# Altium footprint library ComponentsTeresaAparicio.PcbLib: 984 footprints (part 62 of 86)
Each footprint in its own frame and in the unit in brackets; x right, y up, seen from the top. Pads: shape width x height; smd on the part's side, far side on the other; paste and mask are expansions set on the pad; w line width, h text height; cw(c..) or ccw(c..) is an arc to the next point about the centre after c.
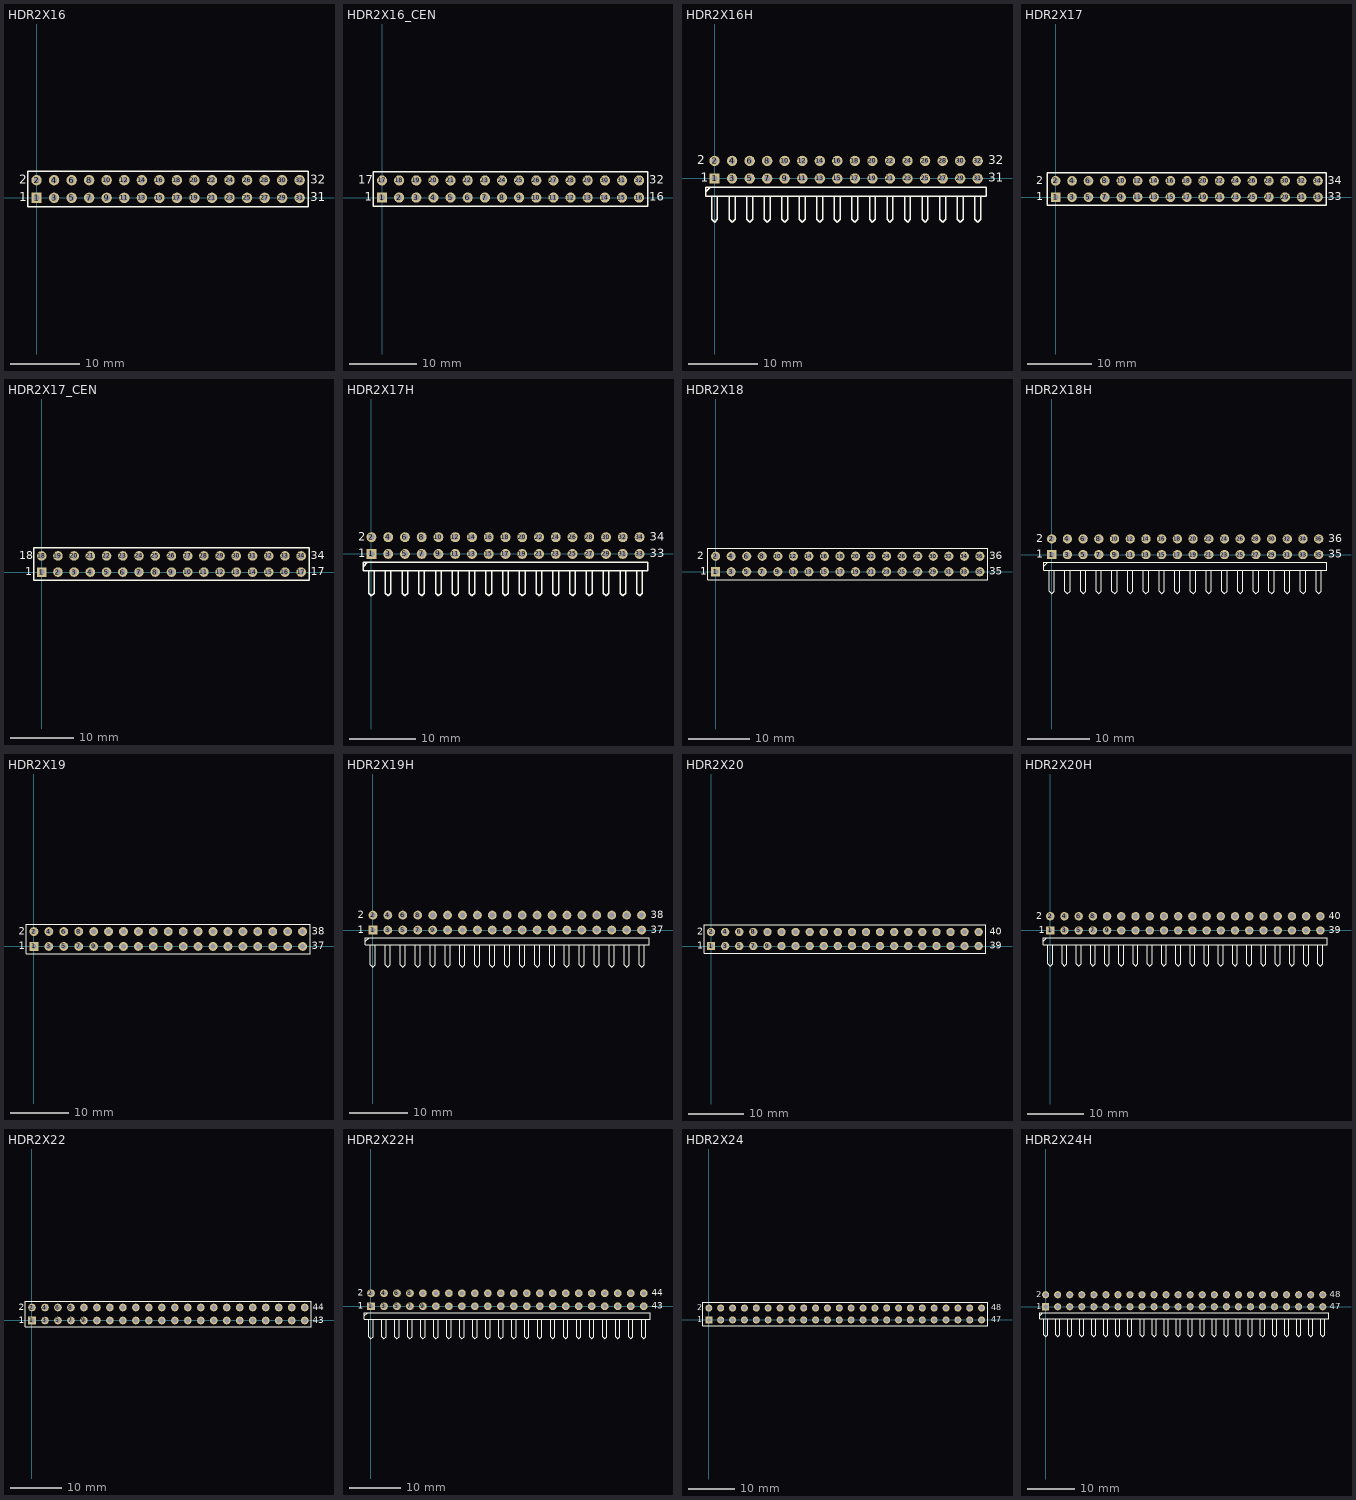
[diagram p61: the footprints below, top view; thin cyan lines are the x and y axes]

## HDR2X16 [mm] "Connector; Header; 16x2 Position"
pads (32):
  rect 1.5x1.5 hole 0.9: 1(0,0)
  round 1.5 hole 0.9: 2(0,2.54) 3(2.54,0) 4(2.54,2.54) 5(5.08,0) 6(5.08,2.54) 7(7.62,0) 8(7.62,2.54) 9(10.16,0) 10(10.16,2.54) 11(12.7,0) 12(12.7,2.54) 13(15.24,0) 14(15.24,2.54) 15(17.78,0) 16(17.78,2.54) 17(20.32,0) 18(20.32,2.54) 19(22.86,0) 20(22.86,2.54) 21(25.4,0) 22(25.4,2.54) 23(27.94,0) 24(27.94,2.54) 25(30.48,0) 26(30.48,2.54) 27(33.02,0) 28(33.02,2.54) 29(35.56,0) 30(35.56,2.54) 31(38.1,0) 32(38.1,2.54)
Top Overlay:
  lines w0.2: -1.27,-1.27 -1.27,3.81 39.37,3.81 39.37,-1.27 -1.27,-1.27
  text "32" at 39.624,2.032 h1.27
  text "31" at 39.624,-0.508 h1.27
  text "1" at -2.54,-0.508 h1.27
  text "2" at -2.54,2.032 h1.27

## HDR2X16_CEN [mm] "Connector; Header; 16x2 Position"
pads (32):
  rect 1.5x1.5 hole 0.9: 1(0,0)
  round 1.5 hole 0.9: 2(2.54,0) 3(5.08,0) 4(7.62,0) 5(10.16,0) 6(12.7,0) 7(15.24,0) 8(17.78,0) 9(20.32,0) 10(22.86,0) 11(25.4,0) 12(27.94,0) 13(30.48,0) 14(33.02,0) 15(35.56,0) 16(38.1,0) 17(0,2.54) 18(2.54,2.54) 19(5.08,2.54) 20(7.62,2.54) 21(10.16,2.54) 22(12.7,2.54) 23(15.24,2.54) 24(17.78,2.54) 25(20.32,2.54) 26(22.86,2.54) 27(25.4,2.54) 28(27.94,2.54) 29(30.48,2.54) 30(33.02,2.54) 31(35.56,2.54) 32(38.1,2.54)
Top Overlay:
  lines w0.2: -1.27,-1.27 39.37,-1.27 39.37,3.81 -1.27,3.81 -1.27,-1.27
  text "17" at -3.556,2.032 h1.27
  text "1" at -2.54,-0.508 h1.27
  text "16" at 39.624,-0.508 h1.27
  text "32" at 39.624,2.032 h1.27

## HDR2X16H [mm] "Connector; Header; 16x2 Position; Right Angle"
pads (32):
  rect 1.5x1.5 hole 0.9: 1(0,0)
  round 1.5 hole 0.9: 2(0,2.54) 3(2.54,0) 4(2.54,2.54) 5(5.08,0) 6(5.08,2.54) 7(7.62,0) 8(7.62,2.54) 9(10.16,0) 10(10.16,2.54) 11(12.7,0) 12(12.7,2.54) 13(15.24,0) 14(15.24,2.54) 15(17.78,0) 16(17.78,2.54) 17(20.32,0) 18(20.32,2.54) 19(22.86,0) 20(22.86,2.54) 21(25.4,0) 22(25.4,2.54) 23(27.94,0) 24(27.94,2.54) 25(30.48,0) 26(30.48,2.54) 27(33.02,0) 28(33.02,2.54) 29(35.56,0) 30(35.56,2.54) 31(38.1,0) 32(38.1,2.54)
Top Overlay:
  lines w0.2: -1.27,-1.905 -0.635,-1.27 ; -0.423,-2.54 -0.423,-5.927 0,-6.35 0.423,-5.927 0.423,-2.54 ; 2.117,-2.54 2.117,-5.927 2.54,-6.35 2.963,-5.927 2.963,-2.54 ; 4.657,-2.54 4.657,-5.927 5.08,-6.35 5.503,-5.927 5.503,-2.54 ; 7.197,-2.54 7.197,-5.927 7.62,-6.35 8.043,-5.927 8.043,-2.54 ; 9.737,-2.54 9.737,-5.927 10.16,-6.35 10.583,-5.927 10.583,-2.54 ; 12.277,-2.54 12.277,-5.927 12.7,-6.35 13.123,-5.927 13.123,-2.54 ; 14.817,-2.54 14.817,-5.927 15.24,-6.35 15.663,-5.927 15.663,-2.54 ; 17.357,-2.54 17.357,-5.927 17.78,-6.35 18.203,-5.927 18.203,-2.54 ; 19.897,-2.54 19.897,-5.927 20.32,-6.35 20.743,-5.927 20.743,-2.54 ; 22.437,-2.54 22.437,-5.927 22.86,-6.35 23.283,-5.927 23.283,-2.54 ; 24.977,-2.54 24.977,-5.927 25.4,-6.35 25.823,-5.927 25.823,-2.54 ; 27.517,-2.54 27.517,-5.927 27.94,-6.35 28.363,-5.927 28.363,-2.54 ; 30.057,-2.54 30.057,-5.927 30.48,-6.35 30.903,-5.927 30.903,-2.54 ; 32.597,-2.54 32.597,-5.927 33.02,-6.35 33.443,-5.927 33.443,-2.54 ; 35.137,-2.54 35.137,-5.927 35.56,-6.35 35.983,-5.927 35.983,-2.54 ; 37.677,-2.54 37.677,-5.927 38.1,-6.35 38.523,-5.927 38.523,-2.54 ; -1.27,-2.54 39.37,-2.54 39.37,-1.27 -1.27,-1.27 -1.27,-2.54
  text "32" at 39.624,2.032 h1.27
  text "31" at 39.624,-0.508 h1.27
  text "1" at -2.032,-0.508 h1.27
  text "2" at -2.54,2.032 h1.27

## HDR2X17 [mm] "Connector; Header; 17x2 Position"
pads (34):
  rect 1.5x1.5 hole 0.9: 1(0,0)
  round 1.5 hole 0.9: 2(0,2.54) 3(2.54,0) 4(2.54,2.54) 5(5.08,0) 6(5.08,2.54) 7(7.62,0) 8(7.62,2.54) 9(10.16,0) 10(10.16,2.54) 11(12.7,0) 12(12.7,2.54) 13(15.24,0) 14(15.24,2.54) 15(17.78,0) 16(17.78,2.54) 17(20.32,0) 18(20.32,2.54) 19(22.86,0) 20(22.86,2.54) 21(25.4,0) 22(25.4,2.54) 23(27.94,0) 24(27.94,2.54) 25(30.48,0) 26(30.48,2.54) 27(33.02,0) 28(33.02,2.54) 29(35.56,0) 30(35.56,2.54) 31(38.1,0) 32(38.1,2.54) 33(40.64,0) 34(40.64,2.54)
Top Overlay:
  lines w0.2: -1.27,-1.27 41.91,-1.27 41.91,3.81 -1.27,3.81 -1.27,-1.27
  text "34" at 42.164,2.032 h1.27
  text "33" at 42.164,-0.508 h1.27
  text "1" at -3.048,-0.508 h1.27
  text "2" at -3.048,2.032 h1.27

## HDR2X17_CEN [mm] "Connector; Header; 17x2 Position"
pads (34):
  rect 1.5x1.5 hole 0.9: 1(0,0)
  round 1.5 hole 0.9: 2(2.54,0) 3(5.08,0) 4(7.62,0) 5(10.16,0) 6(12.7,0) 7(15.24,0) 8(17.78,0) 9(20.32,0) 10(22.86,0) 11(25.4,0) 12(27.94,0) 13(30.48,0) 14(33.02,0) 15(35.56,0) 16(38.1,0) 17(40.64,0) 18(0,2.54) 19(2.54,2.54) 20(5.08,2.54) 21(7.62,2.54) 22(10.16,2.54) 23(12.7,2.54) 24(15.24,2.54) 25(17.78,2.54) 26(20.32,2.54) 27(22.86,2.54) 28(25.4,2.54) 29(27.94,2.54) 30(30.48,2.54) 31(33.02,2.54) 32(35.56,2.54) 33(38.1,2.54) 34(40.64,2.54)
Top Overlay:
  lines w0.2: -1.27,-1.27 41.91,-1.27 41.91,3.81 -1.27,3.81 -1.27,-1.27
  text "18" at -3.556,2.032 h1.27
  text "1" at -2.54,-0.508 h1.27
  text "17" at 42.164,-0.508 h1.27
  text "34" at 42.164,2.032 h1.27

## HDR2X17H [mm] "Connector; Header; 17x2 Position; Right Angle"
pads (34):
  rect 1.5x1.5 hole 0.9: 1(0,0)
  round 1.5 hole 0.9: 2(0,2.54) 3(2.54,0) 4(2.54,2.54) 5(5.08,0) 6(5.08,2.54) 7(7.62,0) 8(7.62,2.54) 9(10.16,0) 10(10.16,2.54) 11(12.7,0) 12(12.7,2.54) 13(15.24,0) 14(15.24,2.54) 15(17.78,0) 16(17.78,2.54) 17(20.32,0) 18(20.32,2.54) 19(22.86,0) 20(22.86,2.54) 21(25.4,0) 22(25.4,2.54) 23(27.94,0) 24(27.94,2.54) 25(30.48,0) 26(30.48,2.54) 27(33.02,0) 28(33.02,2.54) 29(35.56,0) 30(35.56,2.54) 31(38.1,0) 32(38.1,2.54) 33(40.64,0) 34(40.64,2.54)
Top Overlay:
  lines w0.2: -1.27,-1.905 -0.635,-1.27 ; -0.423,-2.54 -0.423,-5.927 0,-6.35 0.423,-5.927 0.423,-2.54 ; 2.117,-2.54 2.117,-5.927 2.54,-6.35 2.963,-5.927 2.963,-2.54 ; 4.657,-2.54 4.657,-5.927 5.08,-6.35 5.503,-5.927 5.503,-2.54 ; 7.197,-2.54 7.197,-5.927 7.62,-6.35 8.043,-5.927 8.043,-2.54 ; 9.737,-2.54 9.737,-5.927 10.16,-6.35 10.583,-5.927 10.583,-2.54 ; 12.277,-2.54 12.277,-5.927 12.7,-6.35 13.123,-5.927 13.123,-2.54 ; 14.817,-2.54 14.817,-5.927 15.24,-6.35 15.663,-5.927 15.663,-2.54 ; 17.357,-2.54 17.357,-5.927 17.78,-6.35 18.203,-5.927 18.203,-2.54 ; 19.897,-2.54 19.897,-5.927 20.32,-6.35 20.743,-5.927 20.743,-2.54 ; 22.437,-2.54 22.437,-5.927 22.86,-6.35 23.283,-5.927 23.283,-2.54 ; 24.977,-2.54 24.977,-5.927 25.4,-6.35 25.823,-5.927 25.823,-2.54 ; 27.517,-2.54 27.517,-5.927 27.94,-6.35 28.363,-5.927 28.363,-2.54 ; 30.057,-2.54 30.057,-5.927 30.48,-6.35 30.903,-5.927 30.903,-2.54 ; 32.597,-2.54 32.597,-5.927 33.02,-6.35 33.443,-5.927 33.443,-2.54 ; 35.137,-2.54 35.137,-5.927 35.56,-6.35 35.983,-5.927 35.983,-2.54 ; 37.677,-2.54 37.677,-5.927 38.1,-6.35 38.523,-5.927 38.523,-2.54 ; 40.217,-2.54 40.217,-5.927 40.64,-6.35 41.063,-5.927 41.063,-2.54 ; -1.27,-2.54 -1.27,-1.27 41.91,-1.27 41.91,-2.54 -1.27,-2.54
  text "34" at 42.164,2.032 h1.27
  text "33" at 42.164,-0.508 h1.27
  text "1" at -2.032,-0.508 h1.27
  text "2" at -2.032,2.032 h1.27

## HDR2X18 [mm] "Connector; Header; 18x2 Position"
pads (36):
  rect 1.5x1.5 hole 0.9: 1(0,0)
  round 1.5 hole 0.9: 2(0,2.54) 3(2.54,0) 4(2.54,2.54) 5(5.08,0) 6(5.08,2.54) 7(7.62,0) 8(7.62,2.54) 9(10.16,0) 10(10.16,2.54) 11(12.7,0) 12(12.7,2.54) 13(15.24,0) 14(15.24,2.54) 15(17.78,0) 16(17.78,2.54) 17(20.32,0) 18(20.32,2.54) 19(22.86,0) 20(22.86,2.54) 21(25.4,0) 22(25.4,2.54) 23(27.94,0) 24(27.94,2.54) 25(30.48,0) 26(30.48,2.54) 27(33.02,0) 28(33.02,2.54) 29(35.56,0) 30(35.56,2.54) 31(38.1,0) 32(38.1,2.54) 33(40.64,0) 34(40.64,2.54) 35(43.18,0) 36(43.18,2.54)
Top Overlay:
  lines w0.2: -1.27,-1.27 -1.27,3.81 44.45,3.81 44.45,-1.27 -1.27,-1.27
  text "2" at -3.048,2.032 h1.27
  text "1" at -2.54,-0.508 h1.27
  text "35" at 44.704,-0.508 h1.27
  text "36" at 44.704,2.032 h1.27

## HDR2X18H [mm] "Connector; Header; 18x2 Position; Right Angle"
pads (36):
  rect 1.5x1.5 hole 0.9: 1(0,0)
  round 1.5 hole 0.9: 2(0,2.54) 3(2.54,0) 4(2.54,2.54) 5(5.08,0) 6(5.08,2.54) 7(7.62,0) 8(7.62,2.54) 9(10.16,0) 10(10.16,2.54) 11(12.7,0) 12(12.7,2.54) 13(15.24,0) 14(15.24,2.54) 15(17.78,0) 16(17.78,2.54) 17(20.32,0) 18(20.32,2.54) 19(22.86,0) 20(22.86,2.54) 21(25.4,0) 22(25.4,2.54) 23(27.94,0) 24(27.94,2.54) 25(30.48,0) 26(30.48,2.54) 27(33.02,0) 28(33.02,2.54) 29(35.56,0) 30(35.56,2.54) 31(38.1,0) 32(38.1,2.54) 33(40.64,0) 34(40.64,2.54) 35(43.18,0) 36(43.18,2.54)
Top Overlay:
  lines w0.2: -1.27,-1.905 -0.635,-1.27 ; -0.423,-2.54 -0.423,-5.927 0,-6.35 0.423,-5.927 0.423,-2.54 ; 2.117,-2.54 2.117,-5.927 2.54,-6.35 2.963,-5.927 2.963,-2.54 ; 4.657,-2.54 4.657,-5.927 5.08,-6.35 5.503,-5.927 5.503,-2.54 ; 7.197,-2.54 7.197,-5.927 7.62,-6.35 8.043,-5.927 8.043,-2.54 ; 9.737,-2.54 9.737,-5.927 10.16,-6.35 10.583,-5.927 10.583,-2.54 ; 12.277,-2.54 12.277,-5.927 12.7,-6.35 13.123,-5.927 13.123,-2.54 ; 14.817,-2.54 14.817,-5.927 15.24,-6.35 15.663,-5.927 15.663,-2.54 ; 17.357,-2.54 17.357,-5.927 17.78,-6.35 18.203,-5.927 18.203,-2.54 ; 19.897,-2.54 19.897,-5.927 20.32,-6.35 20.743,-5.927 20.743,-2.54 ; 22.437,-2.54 22.437,-5.927 22.86,-6.35 23.283,-5.927 23.283,-2.54 ; 24.977,-2.54 24.977,-5.927 25.4,-6.35 25.823,-5.927 25.823,-2.54 ; 27.517,-2.54 27.517,-5.927 27.94,-6.35 28.363,-5.927 28.363,-2.54 ; 30.057,-2.54 30.057,-5.927 30.48,-6.35 30.903,-5.927 30.903,-2.54 ; 32.597,-2.54 32.597,-5.927 33.02,-6.35 33.443,-5.927 33.443,-2.54 ; 35.137,-2.54 35.137,-5.927 35.56,-6.35 35.983,-5.927 35.983,-2.54 ; 37.677,-2.54 37.677,-5.927 38.1,-6.35 38.523,-5.927 38.523,-2.54 ; 40.217,-2.54 40.217,-5.927 40.64,-6.35 41.063,-5.927 41.063,-2.54 ; 42.757,-2.54 42.757,-5.927 43.18,-6.35 43.603,-5.927 43.603,-2.54 ; -1.27,-2.54 -1.27,-1.27 44.45,-1.27 44.45,-2.54 -1.27,-2.54
  text "35" at 44.704,-0.508 h1.27
  text "36" at 44.704,2.032 h1.27
  text "2" at -2.54,2.032 h1.27
  text "1" at -2.54,-0.508 h1.27

## HDR2X19 [mm] "Connector; Header; 19x2 Position"
pads (38):
  rect 1.5x1.5 hole 0.9: 1(0,0)
  round 1.5 hole 0.9: 2(0,2.54) 3(2.54,0) 4(2.54,2.54) 5(5.08,0) 6(5.08,2.54) 7(7.62,0) 8(7.62,2.54) 9(10.16,0) 10(10.16,2.54) 11(12.7,0) 12(12.7,2.54) 13(15.24,0) 14(15.24,2.54) 15(17.78,0) 16(17.78,2.54) 17(20.32,0) 18(20.32,2.54) 19(22.86,0) 20(22.86,2.54) 21(25.4,0) 22(25.4,2.54) 23(27.94,0) 24(27.94,2.54) 25(30.48,0) 26(30.48,2.54) 27(33.02,0) 28(33.02,2.54) 29(35.56,0) 30(35.56,2.54) 31(38.1,0) 32(38.1,2.54) 33(40.64,0) 34(40.64,2.54) 35(43.18,0) 36(43.18,2.54) 37(45.72,0) 38(45.72,2.54)
Top Overlay:
  lines w0.2: -1.27,-1.27 -1.27,3.81 46.99,3.81 46.99,-1.27 -1.27,-1.27
  text "38" at 47.244,2.032 h1.27
  text "37" at 47.244,-0.508 h1.27
  text "1" at -2.54,-0.508 h1.27
  text "2" at -2.54,2.032 h1.27

## HDR2X19H [mm] "Connector; Header; 19x2 Position; Right Angle"
pads (38):
  rect 1.5x1.5 hole 0.9: 1(0,0)
  round 1.5 hole 0.9: 2(0,2.54) 3(2.54,0) 4(2.54,2.54) 5(5.08,0) 6(5.08,2.54) 7(7.62,0) 8(7.62,2.54) 9(10.16,0) 10(10.16,2.54) 11(12.7,0) 12(12.7,2.54) 13(15.24,0) 14(15.24,2.54) 15(17.78,0) 16(17.78,2.54) 17(20.32,0) 18(20.32,2.54) 19(22.86,0) 20(22.86,2.54) 21(25.4,0) 22(25.4,2.54) 23(27.94,0) 24(27.94,2.54) 25(30.48,0) 26(30.48,2.54) 27(33.02,0) 28(33.02,2.54) 29(35.56,0) 30(35.56,2.54) 31(38.1,0) 32(38.1,2.54) 33(40.64,0) 34(40.64,2.54) 35(43.18,0) 36(43.18,2.54) 37(45.72,0) 38(45.72,2.54)
Top Overlay:
  lines w0.2: -1.27,-1.905 -0.635,-1.27 ; -0.423,-2.54 -0.423,-5.927 0,-6.35 0.423,-5.927 0.423,-2.54 ; 2.117,-2.54 2.117,-5.927 2.54,-6.35 2.963,-5.927 2.963,-2.54 ; 4.657,-2.54 4.657,-5.927 5.08,-6.35 5.503,-5.927 5.503,-2.54 ; 7.197,-2.54 7.197,-5.927 7.62,-6.35 8.043,-5.927 8.043,-2.54 ; 9.737,-2.54 9.737,-5.927 10.16,-6.35 10.583,-5.927 10.583,-2.54 ; 12.277,-2.54 12.277,-5.927 12.7,-6.35 13.123,-5.927 13.123,-2.54 ; 14.817,-2.54 14.817,-5.927 15.24,-6.35 15.663,-5.927 15.663,-2.54 ; 17.357,-2.54 17.357,-5.927 17.78,-6.35 18.203,-5.927 18.203,-2.54 ; 19.897,-2.54 19.897,-5.927 20.32,-6.35 20.743,-5.927 20.743,-2.54 ; 22.437,-2.54 22.437,-5.927 22.86,-6.35 23.283,-5.927 23.283,-2.54 ; 24.977,-2.54 24.977,-5.927 25.4,-6.35 25.823,-5.927 25.823,-2.54 ; 27.517,-2.54 27.517,-5.927 27.94,-6.35 28.363,-5.927 28.363,-2.54 ; 30.057,-2.54 30.057,-5.927 30.48,-6.35 30.903,-5.927 30.903,-2.54 ; 32.597,-2.54 32.597,-5.927 33.02,-6.35 33.443,-5.927 33.443,-2.54 ; 35.137,-2.54 35.137,-5.927 35.56,-6.35 35.983,-5.927 35.983,-2.54 ; 37.677,-2.54 37.677,-5.927 38.1,-6.35 38.523,-5.927 38.523,-2.54 ; 40.217,-2.54 40.217,-5.927 40.64,-6.35 41.063,-5.927 41.063,-2.54 ; 42.757,-2.54 42.757,-5.927 43.18,-6.35 43.603,-5.927 43.603,-2.54 ; 45.297,-2.54 45.297,-5.927 45.72,-6.35 46.143,-5.927 46.143,-2.54 ; -1.27,-2.54 46.99,-2.54 46.99,-1.27 -1.27,-1.27 -1.27,-2.54
  text "38" at 47.244,2.032 h1.27
  text "37" at 47.244,-0.508 h1.27
  text "1" at -2.54,-0.508 h1.27
  text "2" at -2.54,2.032 h1.27

## HDR2X20 [mm] "Connector; Header; 20x2 Position"
pads (40):
  rect 1.5x1.5 hole 0.9: 1(0,0)
  round 1.5 hole 0.9: 2(0,2.54) 3(2.54,0) 4(2.54,2.54) 5(5.08,0) 6(5.08,2.54) 7(7.62,0) 8(7.62,2.54) 9(10.16,0) 10(10.16,2.54) 11(12.7,0) 12(12.7,2.54) 13(15.24,0) 14(15.24,2.54) 15(17.78,0) 16(17.78,2.54) 17(20.32,0) 18(20.32,2.54) 19(22.86,0) 20(22.86,2.54) 21(25.4,0) 22(25.4,2.54) 23(27.94,0) 24(27.94,2.54) 25(30.48,0) 26(30.48,2.54) 27(33.02,0) 28(33.02,2.54) 29(35.56,0) 30(35.56,2.54) 31(38.1,0) 32(38.1,2.54) 33(40.64,0) 34(40.64,2.54) 35(43.18,0) 36(43.18,2.54) 37(45.72,0) 38(45.72,2.54) 39(48.26,0) 40(48.26,2.54)
Top Overlay:
  lines w0.2: -1.27,-1.27 -1.27,3.81 49.53,3.81 49.53,-1.27 -1.27,-1.27
  text "39" at 50.292,-0.508 h1.27
  text "40" at 50.292,2.032 h1.27
  text "2" at -2.54,2.032 h1.27
  text "1" at -2.54,-0.508 h1.27

## HDR2X20H [mm] "Connector; Header; 20x2 Position; Right Angle"
pads (40):
  rect 1.5x1.5 hole 0.9: 1(0,0)
  round 1.5 hole 0.9: 2(0,2.54) 3(2.54,0) 4(2.54,2.54) 5(5.08,0) 6(5.08,2.54) 7(7.62,0) 8(7.62,2.54) 9(10.16,0) 10(10.16,2.54) 11(12.7,0) 12(12.7,2.54) 13(15.24,0) 14(15.24,2.54) 15(17.78,0) 16(17.78,2.54) 17(20.32,0) 18(20.32,2.54) 19(22.86,0) 20(22.86,2.54) 21(25.4,0) 22(25.4,2.54) 23(27.94,0) 24(27.94,2.54) 25(30.48,0) 26(30.48,2.54) 27(33.02,0) 28(33.02,2.54) 29(35.56,0) 30(35.56,2.54) 31(38.1,0) 32(38.1,2.54) 33(40.64,0) 34(40.64,2.54) 35(43.18,0) 36(43.18,2.54) 37(45.72,0) 38(45.72,2.54) 39(48.26,0) 40(48.26,2.54)
Top Overlay:
  lines w0.2: -1.27,-1.905 -0.635,-1.27 ; -0.423,-2.54 -0.423,-5.927 0,-6.35 0.423,-5.927 0.423,-2.54 ; 2.117,-2.54 2.117,-5.927 2.54,-6.35 2.963,-5.927 2.963,-2.54 ; 4.657,-2.54 4.657,-5.927 5.08,-6.35 5.503,-5.927 5.503,-2.54 ; 7.197,-2.54 7.197,-5.927 7.62,-6.35 8.043,-5.927 8.043,-2.54 ; 9.737,-2.54 9.737,-5.927 10.16,-6.35 10.583,-5.927 10.583,-2.54 ; 12.277,-2.54 12.277,-5.927 12.7,-6.35 13.123,-5.927 13.123,-2.54 ; 14.817,-2.54 14.817,-5.927 15.24,-6.35 15.663,-5.927 15.663,-2.54 ; 17.357,-2.54 17.357,-5.927 17.78,-6.35 18.203,-5.927 18.203,-2.54 ; 19.897,-2.54 19.897,-5.927 20.32,-6.35 20.743,-5.927 20.743,-2.54 ; 22.437,-2.54 22.437,-5.927 22.86,-6.35 23.283,-5.927 23.283,-2.54 ; 24.977,-2.54 24.977,-5.927 25.4,-6.35 25.823,-5.927 25.823,-2.54 ; 27.517,-2.54 27.517,-5.927 27.94,-6.35 28.363,-5.927 28.363,-2.54 ; 30.057,-2.54 30.057,-5.927 30.48,-6.35 30.903,-5.927 30.903,-2.54 ; 32.597,-2.54 32.597,-5.927 33.02,-6.35 33.443,-5.927 33.443,-2.54 ; 35.137,-2.54 35.137,-5.927 35.56,-6.35 35.983,-5.927 35.983,-2.54 ; 37.677,-2.54 37.677,-5.927 38.1,-6.35 38.523,-5.927 38.523,-2.54 ; 40.217,-2.54 40.217,-5.927 40.64,-6.35 41.063,-5.927 41.063,-2.54 ; 42.757,-2.54 42.757,-5.927 43.18,-6.35 43.603,-5.927 43.603,-2.54 ; 45.297,-2.54 45.297,-5.927 45.72,-6.35 46.143,-5.927 46.143,-2.54 ; 47.837,-2.54 47.837,-5.927 48.26,-6.35 48.683,-5.927 48.683,-2.54 ; -1.27,-2.54 -1.27,-1.27 49.53,-1.27 49.53,-2.54 -1.27,-2.54
  text "40" at 49.784,2.032 h1.27
  text "39" at 49.784,-0.508 h1.27
  text "1" at -2.032,-0.508 h1.27
  text "2" at -2.54,2.032 h1.27

## HDR2X22 [mm] "Connector; Header; 22x2 Position"
pads (44):
  rect 1.5x1.5 hole 0.9: 1(0,0)
  round 1.5 hole 0.9: 2(0,2.54) 3(2.54,0) 4(2.54,2.54) 5(5.08,0) 6(5.08,2.54) 7(7.62,0) 8(7.62,2.54) 9(10.16,0) 10(10.16,2.54) 11(12.7,0) 12(12.7,2.54) 13(15.24,0) 14(15.24,2.54) 15(17.78,0) 16(17.78,2.54) 17(20.32,0) 18(20.32,2.54) 19(22.86,0) 20(22.86,2.54) 21(25.4,0) 22(25.4,2.54) 23(27.94,0) 24(27.94,2.54) 25(30.48,0) 26(30.48,2.54) 27(33.02,0) 28(33.02,2.54) 29(35.56,0) 30(35.56,2.54) 31(38.1,0) 32(38.1,2.54) 33(40.64,0) 34(40.64,2.54) 35(43.18,0) 36(43.18,2.54) 37(45.72,0) 38(45.72,2.54) 39(48.26,0) 40(48.26,2.54) 41(50.8,0) 42(50.8,2.54) 43(53.34,0) 44(53.34,2.54)
Top Overlay:
  lines w0.2: -1.27,-1.27 -1.27,3.81 54.61,3.81 54.61,-1.27 -1.27,-1.27
  text "43" at 54.864,-0.508 h1.27
  text "44" at 54.864,2.032 h1.27
  text "1" at -2.54,-0.508 h1.27
  text "2" at -2.54,2.032 h1.27

## HDR2X22H [mm] "Connector; Header; 22x2 Position; Right Angle"
pads (44):
  rect 1.5x1.5 hole 0.9: 1(0,0)
  round 1.5 hole 0.9: 2(0,2.54) 3(2.54,0) 4(2.54,2.54) 5(5.08,0) 6(5.08,2.54) 7(7.62,0) 8(7.62,2.54) 9(10.16,0) 10(10.16,2.54) 11(12.7,0) 12(12.7,2.54) 13(15.24,0) 14(15.24,2.54) 15(17.78,0) 16(17.78,2.54) 17(20.32,0) 18(20.32,2.54) 19(22.86,0) 20(22.86,2.54) 21(25.4,0) 22(25.4,2.54) 23(27.94,0) 24(27.94,2.54) 25(30.48,0) 26(30.48,2.54) 27(33.02,0) 28(33.02,2.54) 29(35.56,0) 30(35.56,2.54) 31(38.1,0) 32(38.1,2.54) 33(40.64,0) 34(40.64,2.54) 35(43.18,0) 36(43.18,2.54) 37(45.72,0) 38(45.72,2.54) 39(48.26,0) 40(48.26,2.54) 41(50.8,0) 42(50.8,2.54) 43(53.34,0) 44(53.34,2.54)
Top Overlay:
  lines w0.2: -1.27,-1.905 -0.635,-1.27 ; -0.423,-2.54 -0.423,-5.927 0,-6.35 0.423,-5.927 0.423,-2.54 ; 2.117,-2.54 2.117,-5.927 2.54,-6.35 2.963,-5.927 2.963,-2.54 ; 4.657,-2.54 4.657,-5.927 5.08,-6.35 5.503,-5.927 5.503,-2.54 ; 7.197,-2.54 7.197,-5.927 7.62,-6.35 8.043,-5.927 8.043,-2.54 ; 9.737,-2.54 9.737,-5.927 10.16,-6.35 10.583,-5.927 10.583,-2.54 ; 12.277,-2.54 12.277,-5.927 12.7,-6.35 13.123,-5.927 13.123,-2.54 ; 14.817,-2.54 14.817,-5.927 15.24,-6.35 15.663,-5.927 15.663,-2.54 ; 17.357,-2.54 17.357,-5.927 17.78,-6.35 18.203,-5.927 18.203,-2.54 ; 19.897,-2.54 19.897,-5.927 20.32,-6.35 20.743,-5.927 20.743,-2.54 ; 22.437,-2.54 22.437,-5.927 22.86,-6.35 23.283,-5.927 23.283,-2.54 ; 24.977,-2.54 24.977,-5.927 25.4,-6.35 25.823,-5.927 25.823,-2.54 ; 27.517,-2.54 27.517,-5.927 27.94,-6.35 28.363,-5.927 28.363,-2.54 ; 30.057,-2.54 30.057,-5.927 30.48,-6.35 30.903,-5.927 30.903,-2.54 ; 32.597,-2.54 32.597,-5.927 33.02,-6.35 33.443,-5.927 33.443,-2.54 ; 35.137,-2.54 35.137,-5.927 35.56,-6.35 35.983,-5.927 35.983,-2.54 ; 37.677,-2.54 37.677,-5.927 38.1,-6.35 38.523,-5.927 38.523,-2.54 ; 40.217,-2.54 40.217,-5.927 40.64,-6.35 41.063,-5.927 41.063,-2.54 ; 42.757,-2.54 42.757,-5.927 43.18,-6.35 43.603,-5.927 43.603,-2.54 ; 45.297,-2.54 45.297,-5.927 45.72,-6.35 46.143,-5.927 46.143,-2.54 ; 47.837,-2.54 47.837,-5.927 48.26,-6.35 48.683,-5.927 48.683,-2.54 ; 50.377,-2.54 50.377,-5.927 50.8,-6.35 51.223,-5.927 51.223,-2.54 ; 52.917,-2.54 52.917,-5.927 53.34,-6.35 53.763,-5.927 53.763,-2.54 ; -1.27,-2.54 -1.27,-1.27 54.61,-1.27 54.61,-2.54 -1.27,-2.54
  text "2" at -2.54,2.032 h1.27
  text "1" at -2.54,-0.508 h1.27
  text "43" at 54.864,-0.508 h1.27
  text "44" at 54.864,2.032 h1.27

## HDR2X24 [mm] "Connector; Header; 24x2 Position"
pads (48):
  rect 1.5x1.5 hole 0.9: 1(0,0)
  round 1.5 hole 0.9: 2(0,2.54) 3(2.54,0) 4(2.54,2.54) 5(5.08,0) 6(5.08,2.54) 7(7.62,0) 8(7.62,2.54) 9(10.16,0) 10(10.16,2.54) 11(12.7,0) 12(12.7,2.54) 13(15.24,0) 14(15.24,2.54) 15(17.78,0) 16(17.78,2.54) 17(20.32,0) 18(20.32,2.54) 19(22.86,0) 20(22.86,2.54) 21(25.4,0) 22(25.4,2.54) 23(27.94,0) 24(27.94,2.54) 25(30.48,0) 26(30.48,2.54) 27(33.02,0) 28(33.02,2.54) 29(35.56,0) 30(35.56,2.54) 31(38.1,0) 32(38.1,2.54) 33(40.64,0) 34(40.64,2.54) 35(43.18,0) 36(43.18,2.54) 37(45.72,0) 38(45.72,2.54) 39(48.26,0) 40(48.26,2.54) 41(50.8,0) 42(50.8,2.54) 43(53.34,0) 44(53.34,2.54) 45(55.88,0) 46(55.88,2.54) 47(58.42,0) 48(58.42,2.54)
Top Overlay:
  lines w0.2: -1.27,-1.27 59.69,-1.27 59.69,3.81 -1.27,3.81 -1.27,-1.27
  text "2" at -2.54,2.032 h1.27
  text "1" at -2.54,-0.508 h1.27
  text "48" at 60.452,2.032 h1.27
  text "47" at 60.452,-0.508 h1.27

## HDR2X24H [mm] "Connector; Header; 24x2 Position; Right Angle"
pads (48):
  rect 1.5x1.5 hole 0.9: 1(0,0)
  round 1.5 hole 0.9: 2(0,2.54) 3(2.54,0) 4(2.54,2.54) 5(5.08,0) 6(5.08,2.54) 7(7.62,0) 8(7.62,2.54) 9(10.16,0) 10(10.16,2.54) 11(12.7,0) 12(12.7,2.54) 13(15.24,0) 14(15.24,2.54) 15(17.78,0) 16(17.78,2.54) 17(20.32,0) 18(20.32,2.54) 19(22.86,0) 20(22.86,2.54) 21(25.4,0) 22(25.4,2.54) 23(27.94,0) 24(27.94,2.54) 25(30.48,0) 26(30.48,2.54) 27(33.02,0) 28(33.02,2.54) 29(35.56,0) 30(35.56,2.54) 31(38.1,0) 32(38.1,2.54) 33(40.64,0) 34(40.64,2.54) 35(43.18,0) 36(43.18,2.54) 37(45.72,0) 38(45.72,2.54) 39(48.26,0) 40(48.26,2.54) 41(50.8,0) 42(50.8,2.54) 43(53.34,0) 44(53.34,2.54) 45(55.88,0) 46(55.88,2.54) 47(58.42,0) 48(58.42,2.54)
Top Overlay:
  lines w0.2: -1.27,-1.905 -0.635,-1.27 ; -0.423,-2.54 -0.423,-5.927 0,-6.35 0.423,-5.927 0.423,-2.54 ; 2.117,-2.54 2.117,-5.927 2.54,-6.35 2.963,-5.927 2.963,-2.54 ; 4.657,-2.54 4.657,-5.927 5.08,-6.35 5.503,-5.927 5.503,-2.54 ; 7.197,-2.54 7.197,-5.927 7.62,-6.35 8.043,-5.927 8.043,-2.54 ; 9.737,-2.54 9.737,-5.927 10.16,-6.35 10.583,-5.927 10.583,-2.54 ; 12.277,-2.54 12.277,-5.927 12.7,-6.35 13.123,-5.927 13.123,-2.54 ; 14.817,-2.54 14.817,-5.927 15.24,-6.35 15.663,-5.927 15.663,-2.54 ; 17.357,-2.54 17.357,-5.927 17.78,-6.35 18.203,-5.927 18.203,-2.54 ; 19.897,-2.54 19.897,-5.927 20.32,-6.35 20.743,-5.927 20.743,-2.54 ; 22.437,-2.54 22.437,-5.927 22.86,-6.35 23.283,-5.927 23.283,-2.54 ; 24.977,-2.54 24.977,-5.927 25.4,-6.35 25.823,-5.927 25.823,-2.54 ; 27.517,-2.54 27.517,-5.927 27.94,-6.35 28.363,-5.927 28.363,-2.54 ; 30.057,-2.54 30.057,-5.927 30.48,-6.35 30.903,-5.927 30.903,-2.54 ; 32.597,-2.54 32.597,-5.927 33.02,-6.35 33.443,-5.927 33.443,-2.54 ; 35.137,-2.54 35.137,-5.927 35.56,-6.35 35.983,-5.927 35.983,-2.54 ; 37.677,-2.54 37.677,-5.927 38.1,-6.35 38.523,-5.927 38.523,-2.54 ; 40.217,-2.54 40.217,-5.927 40.64,-6.35 41.063,-5.927 41.063,-2.54 ; 42.757,-2.54 42.757,-5.927 43.18,-6.35 43.603,-5.927 43.603,-2.54 ; 45.297,-2.54 45.297,-5.927 45.72,-6.35 46.143,-5.927 46.143,-2.54 ; 47.837,-2.54 47.837,-5.927 48.26,-6.35 48.683,-5.927 48.683,-2.54 ; 50.377,-2.54 50.377,-5.927 50.8,-6.35 51.223,-5.927 51.223,-2.54 ; 52.917,-2.54 52.917,-5.927 53.34,-6.35 53.763,-5.927 53.763,-2.54 ; 55.457,-2.54 55.457,-5.927 55.88,-6.35 56.303,-5.927 56.303,-2.54 ; 57.997,-2.54 57.997,-5.927 58.42,-6.35 58.843,-5.927 58.843,-2.54 ; -1.27,-2.54 59.69,-2.54 59.69,-1.27 -1.27,-1.27 -1.27,-2.54
  text "2" at -2.032,2.032 h1.27
  text "1" at -2.032,-0.508 h1.27
  text "47" at 59.944,-0.508 h1.27
  text "48" at 59.944,2.032 h1.27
